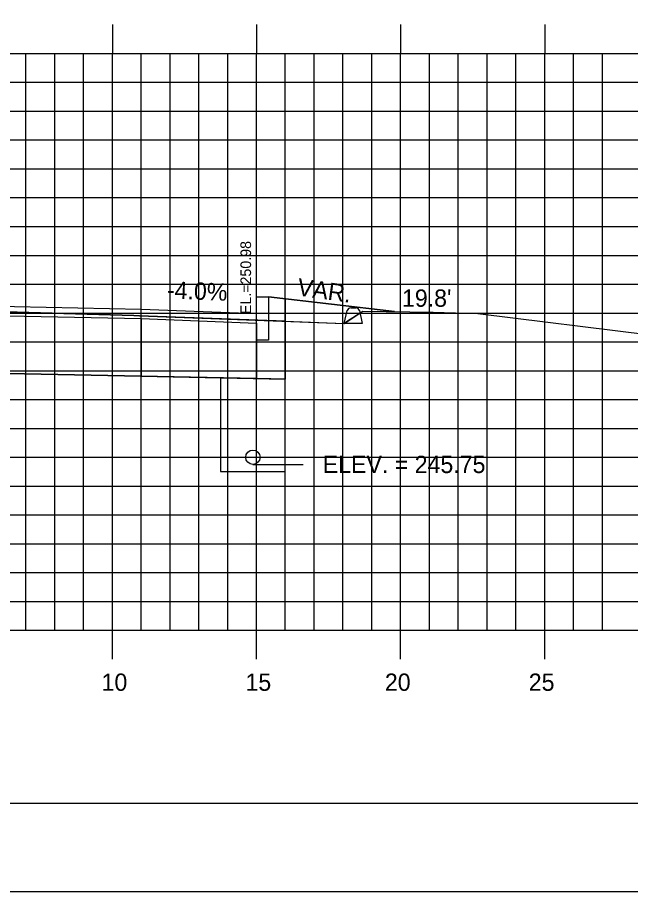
# Model space of a CAD drawing. Extents: x 859575 to 859745, y 366268 to 366378.
# Drawn here: x 859664.5 to 859685.77, y 366268.18 to 366298.48 of the extents above; entities that cross this region are included whole.
import ezdxf

# ---------------------------------------------------------------- set-up
doc = ezdxf.new("R2010")
doc.units = 0
for name, color, linetype in [('ANNOTATION', 7, 'Continuous'), ('BORDER', 7, 'Continuous'), ('D_Curb_Type_1_Rt', 7, 'Continuous'), ('D_Roadway_Edge_Shoulder', 7, 'Continuous'), ('D_Roadway_FinishedGrade', 7, 'Continuous'), ('D_Roadway_SubGrade', 7, 'Continuous'), ('D_Text_Standard', 7, 'Continuous'), ('H_V ANNOTATION', 7, 'Continuous'), ('JUNK COM EXC', 7, 'Continuous'), ('JUNK FILL', 7, 'Continuous'), ('junk strct exc', 7, 'Continuous'), ('MAJOR', 7, 'Continuous'), ('MINOR', 7, 'Continuous'), ('PDRAIN', 7, 'Continuous'), ('PLOT BOUNDARY', 7, 'Continuous'), ('S_Curb_Type_3', 7, 'Continuous'), ('S_Roadway_Centerline', 7, 'Continuous')]:
    doc.layers.add(name, color=color, linetype=linetype)

msp = doc.modelspace()

# ---------------------------------------------------------------- linework, layer by layer
at = {"layer": 'BORDER'}
msp.add_line((859582.797, 366271.236), (859742.797, 366271.236), dxfattribs=at)
at = {"layer": 'D_Curb_Type_1_Rt'}
msp.add_lwpolyline([(859673.214, 366288.799), (859673.214, 366287.299), (859672.798, 366287.299), (859672.798, 366288.799)], close=True, dxfattribs=at)
at = {"layer": 'D_Roadway_Edge_Shoulder'}
msp.add_lwpolyline([(859642.797, 366288.215), (859646.797, 366288.375), (859657.797, 366288.595), (859668.797, 366288.375), (859672.789, 366288.216)], dxfattribs=at)
at = {"layer": 'D_Roadway_FinishedGrade'}
msp.add_lwpolyline([(859673.214, 366288.798), (859677.583, 366288.283)], dxfattribs=at)
at = {"layer": 'D_Roadway_SubGrade'}
msp.add_lwpolyline([(859673.797, 366288.73), (859673.797, 366285.942), (859672.797, 366285.962)], dxfattribs=at)
for points in [[(859646.797, 366286.042), (859646.797, 366288.042), (859657.797, 366288.262), (859668.797, 366288.042), (859668.797, 366286.042), (859657.797, 366286.262)], [(859668.797, 366288.042), (859672.797, 366287.882), (859672.797, 366285.962), (859668.797, 366286.042)]]:
    msp.add_lwpolyline(points, close=True, dxfattribs=at)
at = {"layer": 'D_Text_Standard'}
msp.add_lwpolyline([(859672.672, 366282.986), (859673.736, 366282.986), (859674.416, 366282.986)], dxfattribs=at)
at = {"layer": 'JUNK COM EXC'}
msp.add_lwpolyline([(859657.797, 366286.262), (859668.797, 366286.042), (859673.797, 366285.942), (859673.797, 366287.952), (859669.051, 366288.13), (859668.735, 366288.142), (859668.536, 366288.155), (859659.214, 366288.419)], dxfattribs=at)
at = {"layer": 'JUNK FILL'}
msp.add_lwpolyline([(859673.797, 366287.952), (859675.842, 366287.875), (859676.483, 366288.297), (859677.58, 366288.283), (859677.58, 366288.283), (859673.214, 366288.798), (859673.214, 366287.974), (859673.797, 366287.952)], dxfattribs=at)
at = {"layer": 'junk strct exc'}
msp.add_lwpolyline([(859671.547, 366285.987), (859671.547, 366282.736), (859673.797, 366282.736), (859673.797, 366285.942)], close=True, dxfattribs=at)
at = {"layer": 'MAJOR'}
for p, q in [((859667.797, 366298.238), (859667.797, 366297.236)), ((859672.797, 366298.238), (859672.797, 366297.236)), ((859677.797, 366298.238), (859677.797, 366297.236)), ((859682.797, 366298.238), (859682.797, 366297.236)), ((859587.797, 366297.236), (859727.797, 366297.236)), ((859587.797, 366297.236), (859727.797, 366297.236)), ((859667.797, 366277.236), (859667.797, 366297.236)), ((859672.797, 366277.236), (859672.797, 366297.236)), ((859677.797, 366277.236), (859677.797, 366297.236)), ((859682.797, 366277.236), (859682.797, 366297.236)), ((859587.797, 366292.236), (859727.797, 366292.236)), ((859587.797, 366287.236), (859727.797, 366287.236)), ((859587.797, 366282.236), (859727.797, 366282.236)), ((859587.797, 366277.236), (859727.797, 366277.236)), ((859587.797, 366277.236), (859727.797, 366277.236)), ((859667.797, 366276.234), (859667.797, 366277.236)), ((859672.797, 366276.234), (859672.797, 366277.236)), ((859677.797, 366276.234), (859677.797, 366277.236)), ((859682.797, 366276.234), (859682.797, 366277.236))]:
    msp.add_line(p, q, dxfattribs=at)
at = {"layer": 'MINOR'}
for p, q in [((859664.797, 366277.236), (859664.797, 366297.236)), ((859665.797, 366277.236), (859665.797, 366297.236)), ((859666.797, 366277.236), (859666.797, 366297.236)), ((859668.797, 366277.236), (859668.797, 366297.236)), ((859669.797, 366277.236), (859669.797, 366297.236)), ((859670.797, 366277.236), (859670.797, 366297.236)), ((859671.797, 366277.236), (859671.797, 366297.236)), ((859673.797, 366277.236), (859673.797, 366297.236)), ((859674.797, 366277.236), (859674.797, 366297.236)), ((859675.797, 366277.236), (859675.797, 366297.236)), ((859676.797, 366277.236), (859676.797, 366297.236)), ((859678.797, 366277.236), (859678.797, 366297.236)), ((859679.797, 366277.236), (859679.797, 366297.236)), ((859680.797, 366277.236), (859680.797, 366297.236)), ((859681.797, 366277.236), (859681.797, 366297.236)), ((859683.797, 366277.236), (859683.797, 366297.236)), ((859684.797, 366277.236), (859684.797, 366297.236)), ((859587.797, 366296.236), (859727.797, 366296.236)), ((859587.797, 366295.236), (859727.797, 366295.236)), ((859587.797, 366294.236), (859727.797, 366294.236)), ((859587.797, 366293.236), (859727.797, 366293.236)), ((859587.797, 366291.236), (859727.797, 366291.236)), ((859587.797, 366290.236), (859727.797, 366290.236)), ((859587.797, 366289.236), (859727.797, 366289.236)), ((859587.797, 366288.236), (859727.797, 366288.236)), ((859587.797, 366286.236), (859727.797, 366286.236)), ((859587.797, 366285.236), (859727.797, 366285.236)), ((859587.797, 366284.236), (859727.797, 366284.236)), ((859587.797, 366283.236), (859727.797, 366283.236)), ((859587.797, 366281.236), (859727.797, 366281.236)), ((859587.797, 366280.236), (859727.797, 366280.236)), ((859587.797, 366279.236), (859727.797, 366279.236)), ((859587.797, 366278.236), (859727.797, 366278.236))]:
    msp.add_line(p, q, dxfattribs=at)
at = {"layer": 'PDRAIN'}
msp.add_lwpolyline([(859671.547, 366285.987), (859671.547, 366282.736), (859673.797, 366282.736), (859673.797, 366285.942)], dxfattribs=at)
msp.add_circle((859672.672, 366283.236), 0.25, dxfattribs=at)
at = {"layer": 'PLOT BOUNDARY'}
msp.add_lwpolyline([(859574.704, 366268.177), (859744.704, 366268.177), (859744.704, 366378.177), (859574.704, 366378.177)], close=True, dxfattribs=at)
at = {"layer": 'S_Curb_Type_3'}
for points in [[(859676.365, 366288.32), (859676.467, 366287.875), (859675.842, 366287.875), (859675.945, 366288.32)], [(859676.067, 366288.417), (859676.243, 366288.417)]]:
    msp.add_lwpolyline(points, dxfattribs=at)
for centre, start, end in [((859676.067, 366288.292), 90, 167.0054), ((859676.243, 366288.292), 12.9946, 90)]:
    msp.add_arc(centre, 0.125, start, end, dxfattribs=at)
at = {"layer": 'S_Roadway_Centerline'}
msp.add_lwpolyline([(859659.214, 366288.419), (859668.536, 366288.155), (859668.735, 366288.142), (859669.051, 366288.13), (859675.842, 366287.875), (859675.916, 366287.939), (859676.483, 366288.297), (859678.924, 366288.266), (859680.477, 366288.214), (859686.457, 366287.48)], dxfattribs=at)

# ---------------------------------------------------------------- texts
at = {"layer": 'ANNOTATION'}
msp.add_text('-4.0%', height=0.6, rotation=357.7098, dxfattribs=at).set_placement((859669.681, 366288.741))
at = {"layer": 'D_Text_Standard'}
for s, height, rotation, p in [(' EL.=250.98', 0.36848, 90, (859672.609, 366288.061)), ('VAR.', 0.6, 352.1154, (859674.185, 366288.849))]:
    msp.add_text(s, height=height, rotation=rotation, dxfattribs=at).set_placement(p)
for s, p in [("19.8'", (859677.844, 366288.453)), ('ELEV. = 245.75', (859675.096, 366282.686))]:
    msp.add_text(s, height=0.6, dxfattribs=at).set_placement(p)
at = {"layer": 'H_V ANNOTATION'}
for s, p in [('10', (859667.423, 366275.136)), ('15', (859672.415, 366275.136)), ('20', (859677.251, 366275.136)), ('25', (859682.243, 366275.136))]:
    msp.add_text(s, height=0.6, dxfattribs=at).set_placement(p)

doc.saveas('drawing.dxf')
